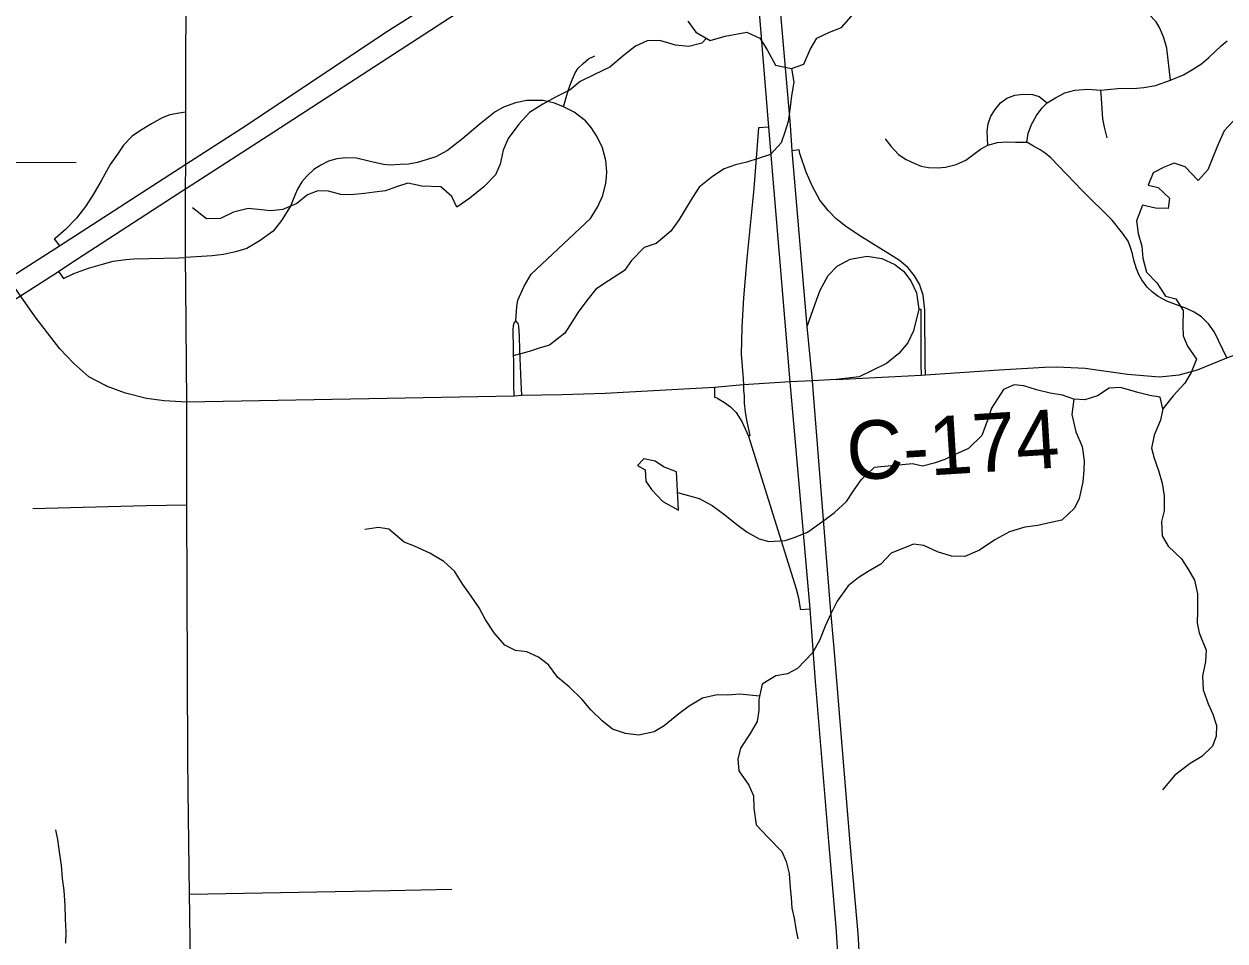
# Model space of a CAD drawing. Extents: x 0 to 34, y 0 to 22.
# Drawn here: x 5.608 to 6.774, y 16.611 to 17.501 of the extents above; entities that cross this region are included whole.
import ezdxf

# ---------------------------------------------------------------- set-up
doc = ezdxf.new("R2010")
doc.units = 0
for name, color, linetype in [('GM_X_City_Street', 7, 'Continuous'), ('GM_X_County_Road', 7, 'Continuous'), ('GM_X_County_Road_Text', 7, 'Continuous'), ('GM_X_Interchange_Ramps', 7, 'Continuous'), ('GM_X_Interstate_Route', 7, 'Continuous'), ('GM_X_Minor_Lake', 7, 'Continuous'), ('GM_X_Minor_River', 7, 'Continuous'), ('GM_X_State_Route', 7, 'Continuous'), ('GM_X_Township_Road', 7, 'Continuous')]:
    doc.layers.add(name, color=color, linetype=linetype)

msp = doc.modelspace()

# ---------------------------------------------------------------- linework, layer by layer
at = {"layer": 'GM_X_City_Street'}
for points in [[(6.1318, 17.421), (6.1351, 17.4325), (6.1381, 17.4413), (6.1402, 17.4474), (6.1431, 17.4541), (6.1462, 17.4585), (6.1509, 17.463), (6.1563, 17.4677), (6.1622, 17.4705)], [(6.0856, 17.2132), (6.0864, 17.2273), (6.0875, 17.2332), (6.0937, 17.247), (6.1006, 17.2586), (6.1581, 17.3127), (6.1648, 17.3237), (6.1702, 17.335), (6.1729, 17.3469), (6.1737, 17.3528), (6.1738, 17.358), (6.1729, 17.3688), (6.1696, 17.3811), (6.1645, 17.3918), (6.1587, 17.4011), (6.1533, 17.4074), (6.1421, 17.416), (6.1318, 17.421), (6.123, 17.4245), (6.112, 17.4272), (6.1026, 17.4273), (6.0961, 17.4273), (6.0853, 17.425), (6.0735, 17.4206), (6.0655, 17.4162), (6.0508, 17.4046), (6.034, 17.3903), (6.0193, 17.3787), (6.0077, 17.3725), (5.9899, 17.3671), (5.9812, 17.3653), (5.9733, 17.365), (5.9637, 17.3645), (5.957, 17.3651), (5.944, 17.3679), (5.9308, 17.3712), (5.9204, 17.3715), (5.9117, 17.3704), (5.9036, 17.3682), (5.896, 17.3645), (5.8893, 17.3601), (5.8827, 17.3542), (5.8778, 17.3483), (5.8735, 17.3412), (5.8705, 17.3342), (5.8667, 17.3245), (5.8579, 17.3106), (5.8497, 17.3004), (5.8373, 17.2911), (5.8241, 17.2836), (5.8133, 17.2803), (5.8015, 17.2775), (5.7905, 17.2763), (5.7647, 17.2748)], [(4.3144, 17.371), (4.4011, 17.3704), (4.565, 17.3697), (4.7306, 17.3693), (4.8313, 17.369), (4.9137, 17.369), (5.0572, 17.3688), (5.2312, 17.368), (5.5132, 17.3677), (5.6583, 17.3669)], [(6.084, 17.1401), (6.0837, 17.1509), (6.0835, 17.1681), (6.0832, 17.1865), (6.083, 17.2041), (6.0833, 17.2087), (6.084, 17.2109), (6.0856, 17.2132)], [(6.0915, 17.1406), (6.0907, 17.1536), (6.0896, 17.1846), (6.0891, 17.1984), (6.0886, 17.2081), (6.0877, 17.2107), (6.0856, 17.2132)], [(5.7659, 17.0342), (5.7264, 17.0336), (5.6163, 17.0305)], [(5.7684, 16.6564), (5.9633, 16.6601), (6.0234, 16.6614)]]:
    msp.add_lwpolyline(points, dxfattribs=at)
at = {"layer": 'GM_X_County_Road'}
for points in [[(5.765, 17.4159), (5.7652, 17.5674), (5.7657, 17.5967), (5.7657, 17.6861), (5.7657, 17.8481), (5.7652, 18.01), (5.7641, 18.0899), (5.763, 18.2502), (5.7624, 18.3939)], [(5.765, 17.2467), (5.7647, 17.2748), (5.7648, 17.3415), (5.7649, 17.3655), (5.765, 17.4159)], [(5.7659, 17.0475), (5.766, 17.1343), (5.765, 17.2467)], [(6.3969, 17.1561), (6.4792, 17.1605), (6.4835, 17.1608), (6.5551, 17.1657), (6.5991, 17.1683), (6.611, 17.1686), (6.6385, 17.1673), (6.6798, 17.1614), (6.7109, 17.1587), (6.7298, 17.1607), (6.7479, 17.1657), (6.7764, 17.1772), (6.8049, 17.1881), (6.8209, 17.1938), (6.8314, 17.197), (6.8397, 17.1986), (6.8472, 17.1994), (6.8548, 17.2001), (6.8677, 17.1991), (6.9249, 17.1872), (6.9884, 17.1736), (7.0275, 17.1723), (7.0591, 17.1724)], [(5.7673, 16.7567), (5.7669, 16.789), (5.7659, 17.0342), (5.7659, 17.0475)], [(5.7687, 16.6365), (5.7684, 16.6564), (5.7673, 16.7567)], [(5.777, 15.8765), (5.7751, 16.0833), (5.7735, 16.2069), (5.7733, 16.2637), (5.7728, 16.3999), (5.7708, 16.4775), (5.7687, 16.6365)]]:
    msp.add_lwpolyline(points, dxfattribs=at)
at = {"layer": 'GM_X_Interchange_Ramps'}
for points in [[(5.765, 17.4159), (5.7586, 17.4148), (5.7493, 17.4133), (5.7421, 17.4104), (5.7317, 17.4046), (5.721, 17.398), (5.7127, 17.3925), (5.7044, 17.3838), (5.6985, 17.3752), (5.6916, 17.3652), (5.6826, 17.3493), (5.6747, 17.3354), (5.6674, 17.3244), (5.6588, 17.313), (5.6481, 17.3019), (5.638, 17.2933), (5.6372, 17.2927), (5.6423, 17.2859)], [(6.3314, 17.4014), (6.3214, 17.4006), (6.3168, 17.3419), (6.3099, 17.2737), (6.3068, 17.2357), (6.305, 17.207), (6.3046, 17.1807), (6.3064, 17.1569), (6.3067, 17.1511)], [(6.4835, 17.1608), (6.4833, 17.1716), (6.4828, 17.2236), (6.4811, 17.2382), (6.4777, 17.2487), (6.4729, 17.2568), (6.4667, 17.2648), (6.4583, 17.2717), (6.4495, 17.2774), (6.4214, 17.2948), (6.4071, 17.3043), (6.3967, 17.3124), (6.3891, 17.3203), (6.381, 17.3304), (6.3736, 17.3437), (6.3676, 17.3577), (6.3616, 17.3757), (6.3608, 17.3792), (6.3541, 17.3784)], [(5.6413, 17.2611), (5.646, 17.2543), (5.6563, 17.2591), (5.6705, 17.2643), (5.684, 17.2684), (5.6944, 17.2712), (5.7068, 17.2729), (5.7144, 17.2735), (5.7583, 17.2745), (5.7647, 17.2748)], [(6.4772, 17.2245), (6.479, 17.2245), (6.479, 17.1712), (6.4792, 17.1605)], [(6.3067, 17.1511), (6.3067, 17.147), (6.3068, 17.1459)], [(6.2784, 17.1485), (6.2787, 17.139), (6.2808, 17.1384), (6.2884, 17.134), (6.294, 17.1298), (6.2997, 17.1241), (6.3052, 17.1154), (6.3115, 17.1013), (6.3579, 16.9529), (6.3602, 16.9443), (6.3619, 16.9339), (6.362, 16.9328), (6.3715, 16.9335)], [(6.3068, 17.1459), (6.3073, 17.1403), (6.3075, 17.1333), (6.3083, 17.1249), (6.3096, 17.1167), (6.313, 17.1018), (6.3115, 17.1013)]]:
    msp.add_lwpolyline(points, dxfattribs=at)
at = {"layer": 'GM_X_Interstate_Route'}
msp.add_line((6.3686, 17.2076), (6.3541, 17.3784), dxfattribs=at)
for points in [[(6.3715, 16.9335), (6.3521, 17.154), (6.3314, 17.4014), (6.3145, 17.6083), (6.307, 17.6922), (6.305, 17.7149), (6.3002, 17.7682), (6.2826, 17.9774), (6.2784, 18.03)], [(4.8864, 16.7942), (4.9942, 16.8641), (5.2351, 17.0208), (5.3596, 17.1019), (5.4573, 17.1656), (5.5341, 17.2164), (5.5926, 17.2543), (5.6423, 17.2859), (5.7649, 17.3655), (5.8238, 17.4034), (5.9593, 17.4935), (6.0809, 17.5707), (6.1115, 17.591), (6.1935, 17.6437), (6.2684, 17.693), (6.305, 17.7149), (6.3251, 17.7268), (6.3491, 17.7401), (6.389, 17.7588), (6.4148, 17.7687), (6.4505, 17.781), (6.4838, 17.7909)], [(6.3541, 17.3784), (6.3523, 17.4032), (6.3342, 17.6119), (6.3323, 17.6353)], [(5.8505, 17.3967), (5.9731, 17.4765), (6.092, 17.5539), (6.1198, 17.5716)], [(5.7631, 17.3404), (5.7648, 17.3415), (5.8349, 17.3866), (5.8505, 17.3967)], [(5.6413, 17.2611), (5.6534, 17.2691), (5.7631, 17.3404)], [(5.5993, 17.2342), (5.6043, 17.2376), (5.6413, 17.2611)], [(6.3749, 17.1382), (6.3736, 17.155), (6.3686, 17.2076)], [(6.4354, 15.896), (6.4325, 16.1103), (6.4307, 16.2396), (6.4291, 16.3704), (6.4281, 16.4267), (6.426, 16.4843), (6.4223, 16.5457), (6.4181, 16.6183), (6.4107, 16.702), (6.3949, 16.8952), (6.3912, 16.9349), (6.3749, 17.1382)], [(6.419, 14.1), (6.4211, 14.4229), (6.425, 14.9668), (6.4239, 15.0701), (6.4187, 15.5636), (6.4161, 15.7761), (6.4147, 15.8905), (6.4116, 16.1673), (6.4105, 16.2537), (6.4089, 16.369), (6.4076, 16.42), (6.4063, 16.4687), (6.4018, 16.5458), (6.3968, 16.6242), (6.3897, 16.7077), (6.3766, 16.863), (6.3715, 16.9335)]]:
    msp.add_lwpolyline(points, dxfattribs=at)
at = {"layer": 'GM_X_Minor_Lake'}
for points in [[(6.2415, 17.0666), (6.2289, 17.0714), (6.2209, 17.077), (6.2099, 17.0792), (6.2039, 17.0727), (6.2111, 17.0686), (6.212, 17.0576), (6.2174, 17.0493), (6.2285, 17.0376), (6.2437, 17.0294)], [(6.2437, 17.0294), (6.2415, 17.0666)]]:
    msp.add_lwpolyline(points, dxfattribs=at)
at = {"layer": 'GM_X_Minor_River'}
for points in [[(6.2527, 17.5044), (6.2604, 17.4935), (6.2742, 17.4856), (6.2889, 17.4896), (6.3101, 17.4936), (6.3227, 17.4876), (6.3296, 17.4763), (6.3377, 17.4615), (6.3533, 17.4583), (6.3654, 17.4625), (6.3714, 17.4767), (6.3781, 17.4877), (6.3902, 17.4936), (6.4019, 17.4982), (6.4136, 17.5113)], [(6.2707, 17.4876), (6.2662, 17.4829), (6.2537, 17.4797), (6.2408, 17.4811), (6.2256, 17.4856), (6.2131, 17.4851), (6.2017, 17.48), (6.1916, 17.4719), (6.1769, 17.4596), (6.1621, 17.4523), (6.1481, 17.4457), (6.1384, 17.4376), (6.124, 17.4306), (6.1119, 17.4237), (6.0987, 17.4156), (6.0886, 17.4041), (6.0781, 17.3903), (6.0732, 17.3789), (6.0703, 17.3655), (6.0659, 17.3549), (6.0546, 17.3434), (6.041, 17.3322), (6.0282, 17.3237), (6.0235, 17.334), (6.0128, 17.3434), (5.9942, 17.3439), (5.9805, 17.3468), (5.9696, 17.3433), (5.959, 17.3394), (5.9484, 17.3382), (5.9385, 17.337), (5.9252, 17.3357), (5.9154, 17.336), (5.9036, 17.3393), (5.8933, 17.3396), (5.8831, 17.3357), (5.8729, 17.3272), (5.8593, 17.3214), (5.8476, 17.3201), (5.8354, 17.3215), (5.8256, 17.3222), (5.8112, 17.3187), (5.7987, 17.3125), (5.785, 17.3123), (5.7713, 17.3229)], [(6.3533, 17.4583), (6.3557, 17.445), (6.3532, 17.4317), (6.3522, 17.4206), (6.35, 17.4069), (6.3471, 17.3974), (6.3434, 17.386), (6.3328, 17.3748), (6.3219, 17.3713), (6.3098, 17.3674), (6.2988, 17.3646), (6.2878, 17.3607), (6.2765, 17.3534), (6.2637, 17.343), (6.2573, 17.3331), (6.2502, 17.3213), (6.2442, 17.3117), (6.236, 17.3002), (6.222, 17.2883), (6.2103, 17.2844), (6.1979, 17.2717), (6.1912, 17.2622), (6.1757, 17.2522), (6.1632, 17.2441), (6.1546, 17.233), (6.146, 17.2215), (6.14, 17.2119), (6.1333, 17.2012), (6.1182, 17.1897), (6.1083, 17.1866), (6.0985, 17.1834), (6.083, 17.1791)], [(6.7824, 17.4072), (6.7737, 17.3976), (6.7681, 17.3854), (6.7629, 17.3728), (6.7577, 17.3598), (6.7484, 17.3495), (6.7357, 17.3627), (6.7251, 17.3664), (6.7153, 17.3625), (6.7047, 17.3571), (6.6999, 17.3449), (6.7094, 17.3427), (6.7205, 17.3325), (6.7194, 17.3223), (6.7069, 17.3225), (6.6944, 17.3254), (6.6884, 17.3102), (6.69, 17.298), (6.6936, 17.2856), (6.6948, 17.2742), (6.6983, 17.2605), (6.7083, 17.25), (6.7167, 17.2372), (6.7266, 17.2346), (6.7339, 17.2233), (6.7336, 17.2085), (6.7337, 17.1986), (6.738, 17.1887), (6.7468, 17.1759), (6.7416, 17.163), (6.7353, 17.1526), (6.724, 17.1404), (6.7142, 17.1278)], [(6.7142, 17.1278), (6.7115, 17.1391), (6.7016, 17.1406), (6.6899, 17.1435), (6.6731, 17.1486), (6.6618, 17.1478), (6.6505, 17.1404), (6.6384, 17.1365), (6.6277, 17.1372), (6.6167, 17.1409), (6.6046, 17.143), (6.5913, 17.1463), (6.5791, 17.15), (6.5696, 17.1511), (6.5594, 17.1464), (6.5475, 17.1285), (6.5434, 17.1159), (6.5382, 17.1018), (6.5254, 17.0891), (6.5122, 17.0833), (6.5024, 17.0787), (6.4918, 17.0751), (6.4805, 17.072), (6.471, 17.0742), (6.4335, 17.0707)], [(6.6277, 17.1372), (6.6256, 17.1224), (6.6295, 17.1053), (6.6357, 17.0913), (6.6377, 17.0773), (6.6374, 17.0678), (6.6364, 17.0568), (6.6327, 17.0408), (6.6283, 17.0312), (6.6159, 17.0197), (6.6053, 17.0173), (6.5928, 17.0146), (6.5799, 17.0129), (6.5652, 17.0082), (6.5508, 17.0005), (6.5361, 16.9905), (6.5218, 16.9843), (6.5089, 16.9845), (6.4952, 16.989), (6.4819, 16.9949), (6.472, 16.9963), (6.4501, 16.9876)], [(6.7142, 17.1278), (6.7117, 17.1167), (6.7057, 17.1022), (6.7032, 17.0897), (6.7056, 17.0798), (6.7098, 17.0677), (6.7134, 17.0556), (6.7154, 17.0431), (6.7155, 17.0286), (6.7129, 17.0184), (6.7134, 17.0043), (6.7192, 16.9945), (6.7322, 16.9821), (6.7391, 16.9715), (6.7449, 16.9613), (6.7476, 16.9481), (6.7478, 16.9313), (6.7475, 16.92), (6.7495, 16.9101), (6.7561, 16.8934), (6.7554, 16.8824), (6.7525, 16.868), (6.7534, 16.8547), (6.758, 16.8414), (6.7627, 16.8312), (6.7662, 16.8202), (6.7659, 16.81), (6.7622, 16.8001), (6.752, 16.7901), (6.7407, 16.7832), (6.7256, 16.772), (6.7136, 16.7578)], [(6.2427, 17.0465), (6.2637, 17.0406), (6.2763, 17.0339), (6.2885, 17.0249), (6.3004, 17.0155), (6.3103, 17.008), (6.3218, 17.0016), (6.3313, 16.999), (6.3472, 16.9999), (6.357, 17.0031), (6.3688, 17.0081), (6.3846, 17.0193), (6.3951, 17.027), (6.4068, 17.0377), (6.4136, 17.0481), (6.421, 17.0588), (6.4335, 17.0707)], [(6.3224, 16.8488), (6.303, 16.8506), (6.2916, 16.8497), (6.281, 16.85), (6.267, 16.8468), (6.2541, 16.8391), (6.244, 16.8314), (6.2297, 16.8199), (6.2198, 16.8141), (6.2051, 16.8109), (6.1921, 16.8123), (6.1796, 16.8167), (6.1693, 16.8246), (6.1585, 16.8355), (6.1501, 16.8453), (6.1375, 16.8578), (6.1264, 16.8668), (6.1172, 16.8792), (6.1076, 16.8867), (6.0962, 16.8916), (6.0852, 16.893), (6.0749, 16.8982), (6.0645, 16.9103), (6.0557, 16.9235), (6.0499, 16.9345), (6.0414, 16.9469), (6.0341, 16.9571), (6.026, 16.97), (6.0157, 16.9794), (6.002, 16.9876), (5.9871, 16.9943), (5.9772, 16.9984), (5.9623, 17.0108), (5.952, 17.0126), (5.9388, 17.0106)], [(6.4501, 16.9876), (6.44, 16.9769), (6.4279, 16.9699), (6.4181, 16.9637), (6.4083, 16.9557), (6.3978, 16.9408), (6.3915, 16.9285), (6.3859, 16.9167), (6.3807, 16.9026), (6.3736, 16.8908), (6.3593, 16.8754), (6.3495, 16.8704), (6.3381, 16.8684), (6.3249, 16.8603), (6.3216, 16.8454), (6.3217, 16.8352), (6.3199, 16.8241), (6.3132, 16.8123), (6.3038, 16.7982), (6.3013, 16.7875), (6.3021, 16.7761), (6.3118, 16.7621), (6.3164, 16.7519), (6.3169, 16.7398), (6.3189, 16.7238), (6.3304, 16.7118), (6.3438, 16.6978), (6.3481, 16.688), (6.3512, 16.6766), (6.3521, 16.6626), (6.353, 16.6531), (6.3538, 16.6428), (6.3558, 16.633), (6.3574, 16.6227), (6.3594, 16.6129)], [(5.6483, 16.6089), (5.6486, 16.6195), (5.6481, 16.6324), (5.6479, 16.6453), (5.6467, 16.6598), (5.6451, 16.6715), (5.6442, 16.6844), (5.6426, 16.6951), (5.6405, 16.7095), (5.6386, 16.719)]]:
    msp.add_lwpolyline(points, dxfattribs=at)
at = {"layer": 'GM_X_State_Route'}
for p, q in [((6.3686, 17.2076), (6.3541, 17.3784)), ((5.687, 17.1503), (5.6709, 17.1589))]:
    msp.add_line(p, q, dxfattribs=at)
for points in [[(6.3541, 17.3784), (6.3523, 17.4032), (6.3342, 17.6119), (6.3323, 17.6353)], [(6.3686, 17.2076), (6.3762, 17.2297), (6.3812, 17.2431), (6.3891, 17.2571), (6.3978, 17.2663), (6.4104, 17.2731), (6.427, 17.276), (6.4412, 17.2737), (6.4536, 17.2679), (6.4623, 17.2613), (6.4694, 17.2521), (6.4748, 17.2405), (6.4772, 17.2245), (6.472, 17.2034), (6.4664, 17.1918), (6.4576, 17.1814), (6.4456, 17.1718), (6.4191, 17.1589), (6.3969, 17.1561)], [(5.6709, 17.1589), (5.6562, 17.1717), (5.6427, 17.1859), (5.6186, 17.2172), (5.6043, 17.2376), (5.5926, 17.2543), (5.5901, 17.2578)], [(6.3749, 17.1382), (6.3736, 17.155), (6.3686, 17.2076)], [(5.7391, 17.1361), (5.7269, 17.1378), (5.7063, 17.1429), (5.6878, 17.1499), (5.687, 17.1503)], [(6.3969, 17.1561), (6.3736, 17.155), (6.3521, 17.154), (6.3067, 17.1511), (6.2784, 17.1485), (6.2489, 17.1469)], [(6.2489, 17.1469), (6.1723, 17.1428), (6.1301, 17.1415), (6.0915, 17.1406), (6.084, 17.1401), (5.766, 17.1343)], [(5.766, 17.1343), (5.7438, 17.1354), (5.7391, 17.1361)], [(6.4354, 15.896), (6.4325, 16.1103), (6.4307, 16.2396), (6.4291, 16.3704), (6.4281, 16.4267), (6.426, 16.4843), (6.4223, 16.5457), (6.4181, 16.6183), (6.4107, 16.702), (6.3949, 16.8952), (6.3912, 16.9349), (6.3749, 17.1382)]]:
    msp.add_lwpolyline(points, dxfattribs=at)
at = {"layer": 'GM_X_Township_Road'}
for points in [[(6.7215, 17.4471), (6.718, 17.478), (6.7152, 17.4881), (6.7112, 17.4974), (6.7075, 17.5035), (6.7004, 17.5111), (6.6937, 17.5191), (6.6822, 17.5316), (6.6743, 17.5405), (6.6713, 17.553), (6.669, 17.566)], [(6.582, 17.3866), (6.5833, 17.3952), (6.5864, 17.4038), (6.5913, 17.4128), (6.5968, 17.42), (6.6016, 17.4251), (6.6098, 17.4299), (6.619, 17.4348), (6.6286, 17.4374), (6.6411, 17.4383), (6.6538, 17.4374), (6.6701, 17.4389), (6.6887, 17.4393), (6.6957, 17.4399), (6.707, 17.4417), (6.7215, 17.4471), (6.7342, 17.4522), (6.743, 17.4572), (6.7516, 17.4629), (6.7586, 17.4685), (6.765, 17.4747), (6.7709, 17.4802), (6.7767, 17.4852)], [(6.5442, 17.3839), (6.5437, 17.3907), (6.5435, 17.3971), (6.5445, 17.4044), (6.547, 17.412), (6.5512, 17.4186), (6.5564, 17.4248), (6.5625, 17.4295), (6.5702, 17.4324), (6.5784, 17.4334), (6.5876, 17.4329), (6.5938, 17.431), (6.6016, 17.4251)], [(6.66, 17.3911), (6.6574, 17.4014), (6.6559, 17.4095), (6.6544, 17.429), (6.6538, 17.4374)], [(6.4442, 17.3899), (6.4498, 17.3829), (6.4573, 17.3748), (6.4649, 17.3699), (6.4731, 17.3659), (6.4794, 17.3634), (6.4866, 17.3621), (6.4952, 17.3618), (6.5031, 17.3626), (6.5133, 17.3651), (6.5227, 17.3694), (6.5305, 17.3751), (6.5368, 17.3799), (6.5442, 17.3839)], [(6.5442, 17.3839), (6.5536, 17.3864), (6.5626, 17.387), (6.571, 17.3868), (6.582, 17.3866)], [(6.7764, 17.1772), (6.7643, 17.2021), (6.7586, 17.2103), (6.7518, 17.217), (6.7446, 17.2217), (6.737, 17.2253), (6.7273, 17.2289), (6.7179, 17.2324), (6.7094, 17.2369), (6.7039, 17.2412), (6.6988, 17.246), (6.6937, 17.253), (6.6911, 17.2576), (6.6884, 17.2638), (6.6859, 17.272), (6.6845, 17.2783), (6.6826, 17.2846), (6.6803, 17.2907), (6.6748, 17.2985), (6.6649, 17.311), (6.6356, 17.3398), (6.6052, 17.3715), (6.5998, 17.3761), (6.5948, 17.3793), (6.5884, 17.3828), (6.582, 17.3866)]]:
    msp.add_lwpolyline(points, dxfattribs=at)

# ---------------------------------------------------------------- texts
at = {"layer": 'GM_X_County_Road_Text'}
msp.add_text('C-174', height=0.05682, rotation=3.544, dxfattribs=at).set_placement((6.4084, 17.0581))

doc.saveas('drawing.dxf')
